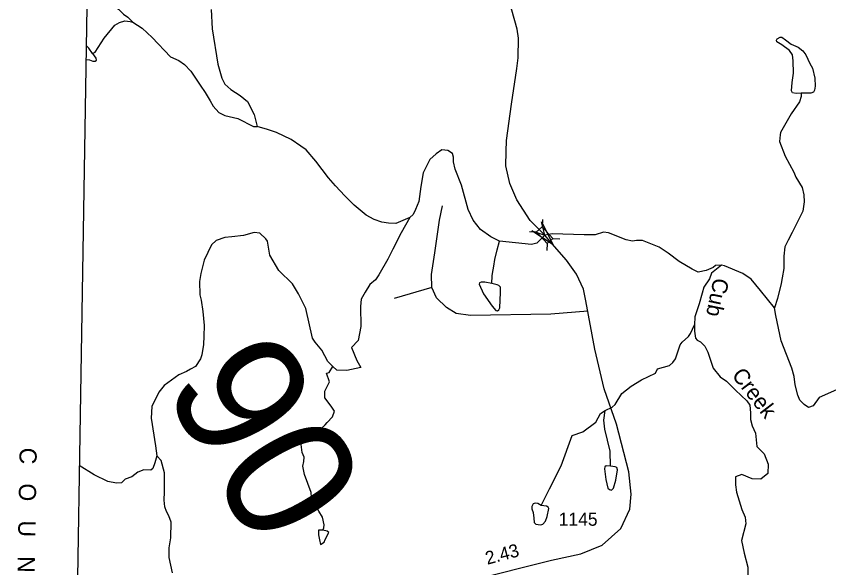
# Model space of a CAD drawing. Extents: x 2056842 to 2160602, y 826753 to 1016856.
# Drawn here: x 2058229 to 2065985, y 933655 to 938922 of the extents above; entities that cross this region are included whole.
import ezdxf

# ---------------------------------------------------------------- set-up
doc = ezdxf.new("R2010")
doc.units = 0
for name, color, linetype in [('Exist Boundary Political CountyLine', 7, 'Continuous'), ('Exist Boundary Political CountyLine Label', 7, 'Continuous'), ('Exist Hydrographic Creek Single Shore', 7, 'Continuous'), ('Exist Hydrographic Creek Single Shore Label', 7, 'Continuous'), ('Exist Hydrographic Misc Water Feature', 7, 'Continuous'), ('Exist Road Non-System Type 51', 7, 'Continuous'), ('Exist Road Secondary Mileage Hundredths English Label', 7, 'Continuous'), ('Exist Road Secondary Structure Standard Bridge Attributed CELL', 7, 'Continuous'), ('Exist Road Secondary Structure Standard Bridge CELL', 7, 'Continuous'), ('Exist Road Secondary Structure Standard Bridge Number Label', 7, 'Continuous'), ('Exist Road Secondary Type 51 Attributed', 7, 'Continuous'), ('Exist Road Secondary Type 51 Number Label', 7, 'Continuous')]:
    doc.layers.add(name, color=color, linetype=linetype)

msp = doc.modelspace()

# ---------------------------------------------------------------- linework, layer by layer
at = {"layer": 'Exist Boundary Political CountyLine'}
msp.add_lwpolyline([(2059856.6, 1016190.3), (2059992.1, 1014583.5), (2060287.9, 1010619.4), (2060242.2, 1008370.9), (2060207.5, 1006770.5), (2060178.3, 1005306.3), (2060151, 1003993.9), (2060126.7, 1003051.7), (2060085.9, 1001469.5), (2060082.6, 1001042.9), (2059970.1, 996247.2), (2059900.3, 992964.9), (2059780.5, 986400.7), (2059706.7, 983126.5), (2059583, 976558.1), (2059387.4, 966719.6), (2059309.7, 963431.4), (2059197.6, 956451.1), (2059161.2, 955539), (2058926.7, 940379.5), (2058724.8, 928102.2), (2058408.1, 910016.3), (2058297.2, 904795.7)], dxfattribs=at)
at = {"layer": 'Exist Hydrographic Creek Single Shore'}
for points in [[(2061985.8, 937000.8), (2061853.4, 936943.5), (2061783.3, 936945.3), (2061717.3, 936955.1), (2061645.3, 936979), (2061569.2, 937022.8), (2061453.4, 937118.3), (2061365.1, 937206.7), (2061276.7, 937300.9), (2061208.6, 937379.2), (2061088.4, 937536), (2060996.1, 937645.8), (2060945.5, 937682.2), (2060852.7, 937744.6), (2060712.2, 937812.7), (2060628.2, 937840.3), (2060529.8, 937869)], [(2062841.8, 936773.2), (2062758.3, 936813.8), (2062661.2, 936883.4), (2062590.2, 936973.3), (2062543.9, 937074.8), (2062480.7, 937308.3), (2062418.2, 937460.2), (2062402, 937532.4), (2062401.9, 937576.4), (2062394.1, 937612.3), (2062350, 937640.1), (2062290.3, 937645.2), (2062236.7, 937609), (2062177.9, 937553.9), (2062114.1, 937426.3), (2062092.4, 937294.4), (2062073.6, 937153.8), (2062038.8, 937075.5), (2062017.6, 937028.4), (2061985.8, 937000.8)], [(2061985.8, 937000.8), (2061903.2, 936854.4), (2061823.5, 936697.8), (2061775.7, 936600.7), (2061691.6, 936453.5), (2061656.9, 936405.7), (2061604.7, 936359.3), (2061561.2, 936286.8), (2061520.7, 936218.7), (2061516.3, 936150.5), (2061519.2, 935958.4), (2061491.7, 935825.1), (2061429.3, 935758.6), (2061479.9, 935635.3), (2061517.5, 935567.7), (2061384.1, 935537.6), (2061290.1, 935541.4), (2061250.7, 935575.2)], [(2061250.7, 935575.2), (2061203.7, 935624.1), (2061147.4, 935733), (2061081.2, 935807.8), (2061057.4, 935847.7), (2060992.7, 936129.6), (2060922.4, 936269.5), (2060866.3, 936365.5), (2060736.1, 936493.2), (2060649.6, 936639.1), (2060627.7, 936773.1), (2060611.5, 936797), (2060554, 936850.8), (2060498.9, 936856.6), (2060397.5, 936829), (2060287.7, 936814.5), (2060219.6, 936808.1), (2060138.4, 936781.2), (2060093.5, 936737.7), (2060022.5, 936592.7), (2059990.3, 936465.7), (2059978.2, 936389.8), (2059982.5, 936261.7), (2059994.5, 936209.6), (2060010.9, 936102.7), (2060024, 935967.9), (2060021.1, 935866.4), (2060016.7, 935788.1), (2060001.4, 935688.8), (2059986.9, 935649.7), (2059940.5, 935577.2), (2059891.3, 935552.5), (2059853.6, 935529.3), (2059781.1, 935497.4), (2059642, 935395.9), (2059589.9, 935332.2), (2059524.7, 935193), (2059517.4, 935082.8), (2059559.1, 934819.1), (2059572.5, 934723.3)], [(2064960, 936543.2), (2064905, 936542.7), (2064881.8, 936522.4), (2064815.1, 936491.9), (2064737.2, 936477.5), (2064680.7, 936505), (2064557.5, 936578.9), (2064453.2, 936660.1), (2064364.8, 936716.7), (2064285.1, 936748.6), (2064208.3, 936779), (2064150.4, 936780.5), (2064113, 936774.7), (2064052.2, 936786.3), (2063882.6, 936852.9), (2063836.3, 936858.7), (2063755.1, 936832.6), (2063649.9, 936832.6), (2063346, 936844.2), (2063273.2, 936830), (2063199.6, 936755.8), (2063148.9, 936741.3), (2062841.8, 936773.2)], [(2064960, 936543.2), (2064865.8, 936467.3), (2064845.6, 936413.7), (2064793.4, 936335.4), (2064777.5, 936277.4), (2064748.5, 936175.9), (2064706.5, 936049.8), (2064702.1, 935974.4)], [(2065467.1, 936136), (2065333.8, 936302), (2065244, 936411.6), (2065164.1, 936463.5), (2064989.7, 936538.9), (2064960, 936543.2)], [(2066058.9, 935355.3), (2065892.8, 935280.7), (2065834.9, 935202.4), (2065792.8, 935185), (2065749.4, 935214), (2065707.4, 935254.6), (2065688.5, 935303.9), (2065663.9, 935402.5), (2065653.9, 935480.4), (2065631.6, 935560.2), (2065530.9, 935821.4), (2065480.2, 936063.5), (2065467.1, 936136)], [(2064702.1, 935974.4), (2064702.1, 935913.5), (2064713.2, 935846.7), (2064729.2, 935826.7), (2064761.3, 935810.6), (2064801.2, 935770.7), (2064829.2, 935714.7), (2064881.5, 935561), (2064949.7, 935476.9), (2065007.9, 935437), (2065096, 935351.1), (2065202.2, 935247.5), (2065231, 935206), (2065236.8, 935133.5), (2065236.8, 935071.2), (2065254.7, 935011.5), (2065284.7, 934939.7), (2065297.6, 934813.8), (2065367.2, 934742.8), (2065406.3, 934642.8), (2065401.9, 934554.3), (2065336.7, 934499.3), (2065252.7, 934505.1), (2065155.4, 934545.3), (2065095.6, 934521.3), (2065095.6, 934445.5), (2065105.7, 934377.3), (2065154.1, 934209.3), (2065186.4, 934137.4), (2065194.2, 934073.6), (2065151.3, 933914.3), (2065178.8, 933795.4), (2065212.1, 933659.8), (2065216.5, 933446.7)], [(2059721.7, 933607.6), (2059689.3, 933751.4), (2059689.1, 933843.4), (2059705.1, 933939.4), (2059706.8, 934091.5), (2059686.7, 934151.4), (2059664.5, 934191.5), (2059648.5, 934235.3), (2059640.3, 934299.3), (2059644.2, 934379.4), (2059643.5, 934560.9), (2059611.6, 934679.8), (2059572.5, 934723.3)]]:
    msp.add_lwpolyline(points, dxfattribs=at)
at = {"layer": 'Exist Hydrographic Misc Water Feature'}
for points in [[(2058908.2, 939283), (2058971.2, 939244), (2059117.6, 939056.3), (2059205.8, 938988.4), (2059253.8, 938940.6), (2059293.8, 938912.6), (2059342, 938864.7)], [(2060090.9, 938984.8), (2060098, 938802.2), (2060154.6, 938462.3), (2060190.9, 938330.3), (2060219, 938274.3), (2060276.4, 938223), (2060366.2, 938165), (2060435.7, 938107), (2060500.9, 937983.8), (2060529.8, 937869)], [(2058957.6, 938565.9), (2058982.5, 938580), (2059068.2, 938712.2), (2059169.9, 938836.4), (2059213.8, 938860.5), (2059265.9, 938876.5), (2059318, 938872.7), (2059342, 938864.7)], [(2059342, 938864.7), (2059429.9, 938806.9), (2059526.3, 938719), (2059700.6, 938533.3), (2059782.6, 938497.5), (2059834.7, 938461.6), (2059894.8, 938397.7), (2059985, 938261.9), (2060033, 938192.5), (2060081.2, 938114.1), (2060109.5, 938062.1), (2060161.6, 938002.2), (2060221.4, 937974.4), (2060345.7, 937944.6), (2060493.7, 937868.9), (2060529.8, 937869)], [(2065722.1, 938186.7), (2065672.9, 938182.4), (2065638.1, 938191.1), (2065630.9, 938208.5), (2065635.2, 938288.2), (2065648.2, 938376.6), (2065646.8, 938497), (2065638.1, 938553.5), (2065609.1, 938595.5), (2065538.1, 938647.7), (2065490.3, 938676.7), (2065486, 938694.1), (2065493.2, 938704.3), (2065520.7, 938720.2), (2065536.7, 938720.2), (2065572.9, 938695.6), (2065625.1, 938656.4), (2065693.2, 938626), (2065738.1, 938592.6), (2065767, 938552.1), (2065804.7, 938469.4), (2065829.4, 938425.9), (2065851.1, 938328.8), (2065854, 938254.9), (2065849.6, 938214.3), (2065839.5, 938196.9), (2065813.4, 938186.7), (2065722.1, 938186.7)], [(2058957.6, 938565.9), (2058922.8, 938615.1), (2058897.4, 938642.9)], [(2058957.6, 938565.9), (2058988, 938520.9), (2058992.4, 938503.5), (2058983.7, 938490.5), (2058963.4, 938489), (2058931.5, 938502.1), (2058895, 938504.5)], [(2065722.1, 938186.7), (2065720.9, 938156.5), (2065705.1, 938104.5), (2065625.4, 937988.4), (2065525.5, 937812.2), (2065519.8, 937788.2), (2065515.7, 937724.2), (2065568.2, 937584.2), (2065650.4, 937432.4), (2065671.4, 937385.7), (2065732.3, 937286.4), (2065746.8, 937216.8), (2065749.7, 937148.7), (2065738.1, 937060.3), (2065635.2, 936856.6), (2065599, 936784.1), (2065565.7, 936718.8), (2065555.5, 936629), (2065555.5, 936513), (2065541, 936424.5), (2065532.3, 936368), (2065494.7, 936227.4), (2065467.1, 936136)], [(2062767.9, 936370.2), (2062770.8, 936441.2), (2062775.1, 936465.9), (2062788.2, 936535.4), (2062796.8, 936599.2), (2062820, 936690.6), (2062841.8, 936773.2)], [(2062767.9, 936370.2), (2062702.7, 936383.2), (2062666.4, 936383.2), (2062652, 936376), (2062649.1, 936361.5), (2062689.6, 936270.1), (2062770.8, 936154.2), (2062808.4, 936112.1), (2062824.4, 936109.2), (2062836, 936116.5), (2062846.1, 936135.3), (2062850.5, 936283.2), (2062850.5, 936333.9), (2062836, 936349.9), (2062818.6, 936357.1), (2062767.9, 936370.2)], [(2063850.7, 935157.1), (2063918.5, 935189.3), (2063946.4, 935213.3), (2064010.2, 935317.4), (2064098.2, 935389.6), (2064198, 935449.8), (2064329.9, 935514), (2064351.8, 935554), (2064465.8, 935586.3), (2064497.8, 935614.3), (2064521.6, 935650.4), (2064565.5, 935782.5), (2064585.4, 935810.5), (2064645.2, 935862.6), (2064665.3, 935890.6), (2064702.1, 935974.4)], [(2061156.9, 934012.1), (2061164.9, 934036.1), (2061168.8, 934064.2), (2061152.6, 934136.2), (2061116.5, 934196.1), (2061048.2, 934327.9), (2061044.1, 934371.9), (2060979.9, 934543.8), (2060963.7, 934623.8), (2060975.6, 934667.8), (2060977.5, 934711.8), (2060959.6, 934755.8), (2060943.2, 934883.7), (2060955.1, 934915.7), (2060967.2, 934925.8), (2061069.1, 934952), (2061137, 934980.1), (2061177.9, 935019), (2061196.9, 935040.2), (2061248.9, 935094.4), (2061267.7, 935150.9), (2061234.6, 935196.2), (2061174.5, 935276.2), (2061174.3, 935340.2), (2061220.6, 935428.6), (2061190.5, 935511.3), (2061216.8, 935518.8), (2061250.7, 935575.2)], [(2063240.5, 934250.6), (2063320, 934408.2), (2063429.7, 934628.4), (2063535.1, 934918.6), (2063639, 934952.8), (2063760.8, 935045), (2063806.6, 935129.1), (2063850.7, 935157.1)], [(2063901.2, 934624.7), (2063899.5, 934769.2), (2063847, 934979.2), (2063838.8, 935065.1), (2063850.7, 935157.1)], [(2059572.5, 934723.3), (2059551.3, 934655.1), (2059532.5, 934601.5), (2059515.1, 934585.5), (2059448.5, 934588.4), (2059389.1, 934568.1), (2059332.6, 934523.2), (2059267.4, 934501.4), (2059234, 934466.7), (2059186.2, 934462.3), (2059103.6, 934479.7), (2058972.4, 934540.6), (2058829.6, 934630.5)], [(2063901.2, 934624.7), (2063859.2, 934627.6), (2063849, 934618.9), (2063843.2, 934598.6), (2063856.3, 934498.5), (2063875.1, 934415.9), (2063891, 934401.4), (2063911.3, 934397), (2063928.7, 934415.9), (2063953.3, 934491.3), (2063967.8, 934589.9), (2063962, 934611.6), (2063947.5, 934618.9), (2063901.2, 934624.7)], [(2063240.5, 934250.6), (2063207.2, 934266.6), (2063181.1, 934272.4), (2063162.3, 934263.7), (2063149.2, 934239), (2063152.1, 934218.7), (2063163.7, 934181), (2063169.5, 934128.8), (2063172.4, 934086.8), (2063189.8, 934069.4), (2063211.5, 934066.5), (2063237.6, 934065.1), (2063255, 934070.9), (2063279.6, 934098.4), (2063298.4, 934143.3), (2063311.5, 934220.2), (2063305.7, 934233.2), (2063291.2, 934241.9), (2063240.5, 934250.6)], [(2061156.9, 934012.1), (2061113, 934012.1), (2061113, 933968.2), (2061123.1, 933922.1)], [(2061179, 933924.3), (2061212.9, 933992.2), (2061196.9, 934004.2), (2061156.9, 934012.1)], [(2061123.1, 933922.1), (2061133.1, 933876.1), (2061169, 933900.2), (2061179, 933924.3)]]:
    msp.add_lwpolyline(points, dxfattribs=at)
at = {"layer": 'Exist Road Non-System Type 51'}
msp.add_line((2062195.1, 936331.6), (2061835.9, 936227.4), dxfattribs=at)
for points in [[(2062195.1, 936331.6), (2062191.5, 936453.8), (2062223.8, 936662.3), (2062270.5, 936974.9), (2062299.2, 937111.5)], [(2063684.1, 936106.5), (2063333.6, 936076.4), (2062565, 936062.1), (2062428.5, 936083.6), (2062335.1, 936141.1), (2062241.8, 936231), (2062195.1, 936331.6)]]:
    msp.add_lwpolyline(points, dxfattribs=at)
at = {"layer": 'Exist Road Secondary Structure Standard Bridge Attributed CELL'}
msp.add_lwpolyline([(2063244.1, 936956.6), (2063354.7, 936739.3), (2063150.3, 936872.2), (2063273.2, 936830)], close=True, dxfattribs=at)
at = {"layer": 'Exist Road Secondary Structure Standard Bridge CELL'}
for p, q in [((2063252.4, 936979.8), (2063248.8, 936910.9)), ((2063127.5, 936867.2), (2063196.4, 936863.6)), ((2063298.5, 936752.2), (2063294.9, 936683.3)), ((2063349.7, 936798.4), (2063418.6, 936794.8))]:
    msp.add_line(p, q, dxfattribs=at)
msp.add_lwpolyline([(2063248.8, 936910.9), (2063350, 936798.6), (2063297.6, 936751.4), (2063196.4, 936863.6)], close=True, dxfattribs=at)
at = {"layer": 'Exist Road Secondary Type 51 Attributed'}
for points in [[(2063273.2, 936830), (2063135.8, 936971.2), (2063008.7, 937167.2), (2062939.9, 937324), (2062903.2, 937492.1), (2062905.5, 937628.8), (2062909.9, 937734.9), (2062957.8, 938080.5), (2063008.2, 938422.1), (2063019.4, 938524.5), (2063022.6, 938711.7), (2063009.8, 938799.7), (2062959.4, 938978.2), (2062866.7, 939223), (2062702.8, 939609.4), (2062662.8, 939737.4), (2062630.8, 939841.4), (2062614.8, 939921.4), (2062594, 940064.7), (2062589.2, 940402.3), (2062588, 940837.9), (2062588, 940957.1), (2062588.8, 941094.7)], [(2062566.5, 933532.2), (2063338.1, 933726.6), (2063618, 933789), (2063821.1, 933870.7), (2064000.2, 934030.7), (2064086.5, 934213.1), (2064099.3, 934357.1), (2064076.9, 934570), (2063957.8, 935025.2), (2063842.7, 935364.5), (2063752.3, 935741.4), (2063666, 936203.8), (2063645.2, 936314.3), (2063578, 936458.3), (2063482.1, 936592.7), (2063322.9, 936772.7), (2063273.2, 936830)]]:
    msp.add_lwpolyline(points, dxfattribs=at)

# ---------------------------------------------------------------- texts
at = {"layer": 'Exist Boundary Political CountyLine Label'}
msp.add_text('C   O   U   N   T     Y', height=164.042, rotation=269.03226, dxfattribs=at).set_placement((2058261.2, 934802.6))
at = {"layer": 'Exist Hydrographic Creek Single Shore Label'}
for s, rotation, p in [('Cub', 258.31971, (2064887.7, 936430.3)), ('Creek', 307.61271, (2065052.8, 935491.7))]:
    msp.add_text(s, height=150, rotation=rotation, dxfattribs=at).set_placement(p)
at = {"layer": 'Exist Road Secondary Mileage Hundredths English Label'}
msp.add_text('2.43', height=125, rotation=14.97504, dxfattribs=at).set_placement((2062725.1, 933682.5))
at = {"layer": 'Exist Road Secondary Structure Standard Bridge Number Label'}
msp.add_text('90', height=1230.31, rotation=300, dxfattribs=at).set_placement((2059617.2, 935385.5))
at = {"layer": 'Exist Road Secondary Type 51 Number Label'}
msp.add_text('1145', height=125, dxfattribs=at).set_placement((2063406.5, 934055.7))

doc.saveas('drawing.dxf')
